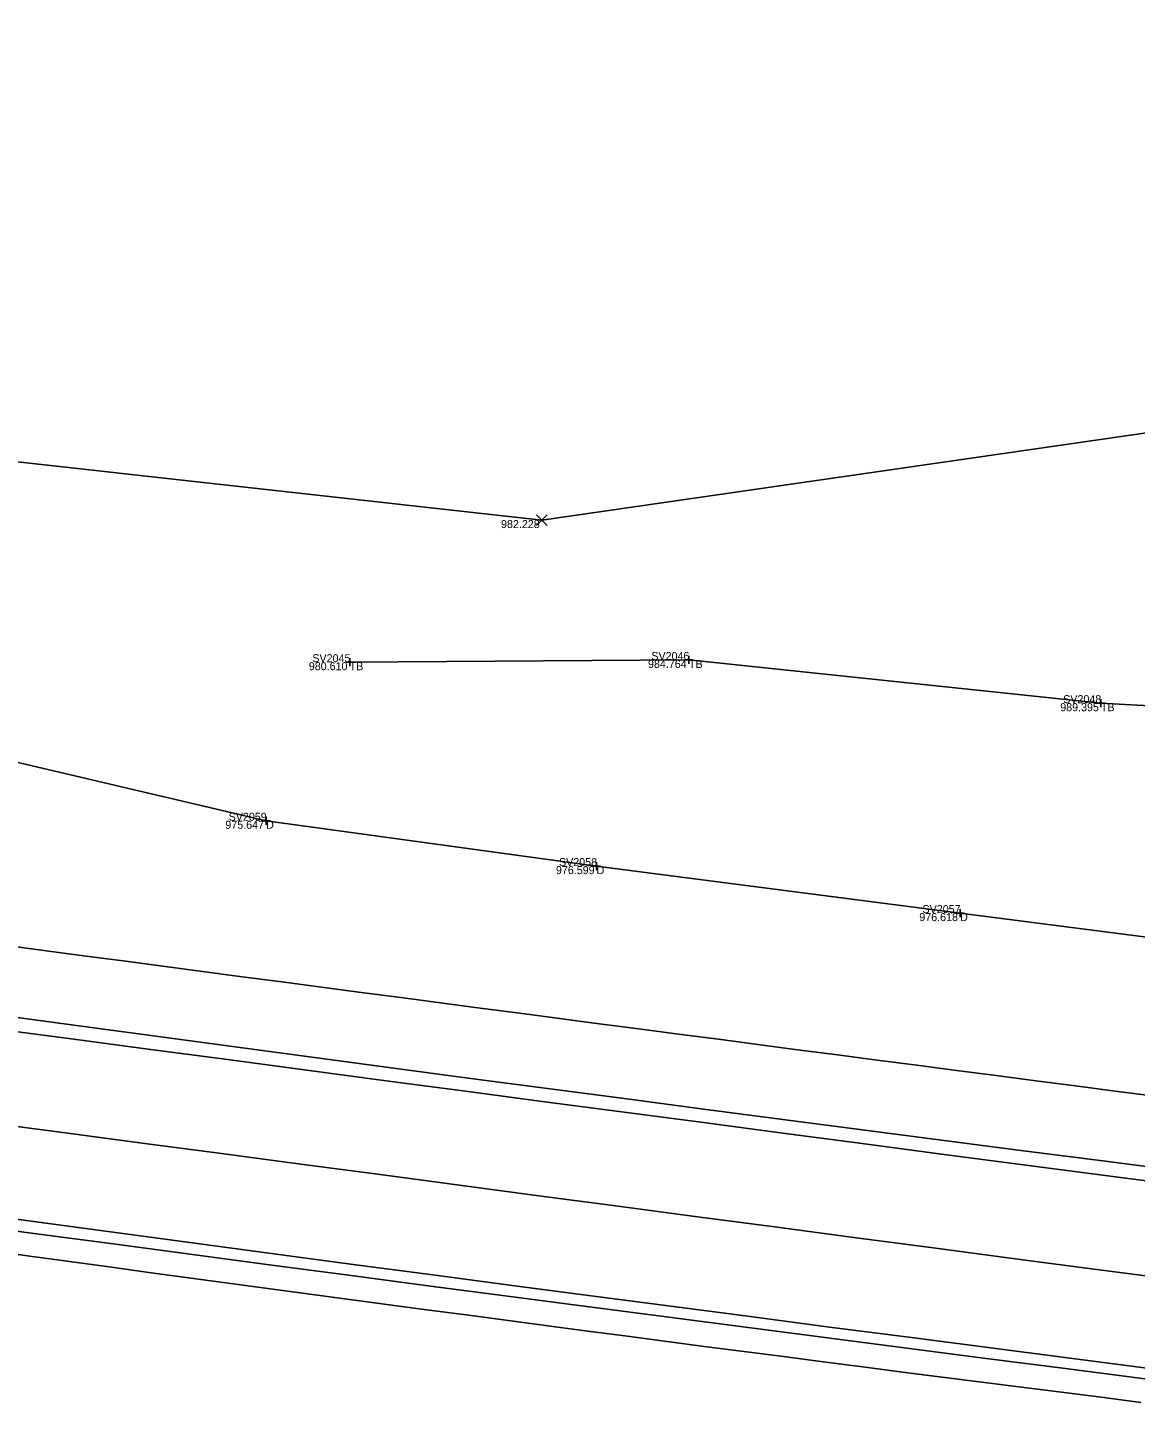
# Model space of a CAD drawing. Extents: x 2065431 to 2068157, y 709104 to 709719.
# Drawn here: x 2066585.2 to 2066723.6, y 709474.3 to 709646.1 of the extents above; entities that cross this region are included whole.
import ezdxf

# ---------------------------------------------------------------- set-up
doc = ezdxf.new("R2010")
doc.units = 0
for name, color, linetype in [('DT_X_Terrain_Boundary', 7, 'Continuous'), ('PM_X_Edge_Line', 7, 'Continuous'), ('PM_X_Lane_Line', 7, 'Continuous'), ('PV_X_EOP', 7, 'Continuous'), ('PV_X_Shoulder_Rumble_Strip', 7, 'Continuous'), ('RS_Raster1', 7, 'Continuous'), ('RW_X_CL_100_Bearings', 7, 'Continuous'), ('RW_X_Fee_WL', 7, 'Continuous'), ('SV_X_Mon_Cells_Found', 7, 'Continuous'), ('SV_X_Text_Elevation', 7, 'Continuous'), ('SV_X_Text_Name', 7, 'Continuous'), ('SV_X_Top_of_Bank', 7, 'Continuous')]:
    doc.layers.add(name, color=color, linetype=linetype)

msp = doc.modelspace()

# ---------------------------------------------------------------- linework, layer by layer
at = {"layer": 'DT_X_Terrain_Boundary'}
msp.add_lwpolyline([(2066859.95, 709495.56), (2066834.34, 709517.99), (2066832.56, 709534.67), (2066834.65, 709554.72), (2066795.22, 709561.14), (2066752.69, 709599.48), (2066649.44, 709584.58), (2066543.44, 709596.37)], dxfattribs=at)
at = {"layer": 'PM_X_Edge_Line'}
for points in [[(2066580.41, 709521.11), (2066590.32, 709519.79), (2066600.23, 709518.47), (2066610.15, 709517.16), (2066620.06, 709515.84), (2066629.97, 709514.53), (2066639.89, 709513.22), (2066649.8, 709511.91), (2066659.71, 709510.6), (2066669.63, 709509.29), (2066679.54, 709507.98), (2066689.46, 709506.67), (2066699.37, 709505.36), (2066709.29, 709504.06), (2066719.2, 709502.76), (2066729.12, 709501.47)], [(2066576.33, 709498.23), (2066586.24, 709496.89), (2066596.15, 709495.55), (2066606.06, 709494.22), (2066615.97, 709492.9), (2066625.88, 709491.58), (2066635.8, 709490.26), (2066645.71, 709488.95), (2066655.62, 709487.65), (2066665.54, 709486.34), (2066675.45, 709485.05), (2066685.37, 709483.75), (2066695.29, 709482.47), (2066705.2, 709481.18), (2066715.12, 709479.91), (2066725.04, 709478.63)]]:
    msp.add_lwpolyline(points, dxfattribs=at)
at = {"layer": 'PM_X_Lane_Line'}
msp.add_lwpolyline([(2066579.69, 709509.37), (2066589.6, 709508.05), (2066599.51, 709506.74), (2066609.42, 709505.42), (2066619.34, 709504.1), (2066629.25, 709502.79), (2066639.16, 709501.47), (2066649.08, 709500.16), (2066658.99, 709498.85), (2066668.9, 709497.53), (2066678.82, 709496.22), (2066688.73, 709494.91), (2066698.65, 709493.6), (2066708.56, 709492.29), (2066718.47, 709490.98), (2066728.39, 709489.68)], dxfattribs=at)
at = {"layer": 'PV_X_EOP'}
for points in [[(2066582.26, 709531.46), (2066587.21, 709530.8), (2066592.17, 709530.15), (2066597.13, 709529.49), (2066602.08, 709528.83), (2066607.04, 709528.18), (2066612, 709527.52), (2066616.96, 709526.87), (2066621.91, 709526.21), (2066626.87, 709525.56), (2066631.83, 709524.91), (2066636.78, 709524.25), (2066641.74, 709523.6), (2066646.7, 709522.95), (2066651.66, 709522.3), (2066656.61, 709521.65), (2066661.57, 709521), (2066666.53, 709520.35), (2066671.49, 709519.7), (2066676.44, 709519.05), (2066681.4, 709518.4), (2066686.36, 709517.76), (2066691.32, 709517.11), (2066696.28, 709516.46), (2066701.23, 709515.82), (2066706.19, 709515.17), (2066711.15, 709514.53), (2066716.11, 709513.89), (2066721.07, 709513.24), (2066726.03, 709512.6)], [(2066580.52, 709493.3), (2066585.47, 709492.62), (2066590.43, 709491.94), (2066595.38, 709491.26), (2066600.33, 709490.58), (2066605.29, 709489.91), (2066610.24, 709489.24), (2066615.2, 709488.57), (2066620.15, 709487.9), (2066625.11, 709487.24), (2066630.06, 709486.58), (2066635.02, 709485.91), (2066639.98, 709485.26), (2066644.93, 709484.6), (2066649.89, 709483.94), (2066654.85, 709483.29), (2066659.81, 709482.64), (2066664.76, 709481.99), (2066669.72, 709481.34), (2066674.68, 709480.7), (2066679.64, 709480.05), (2066684.6, 709479.41), (2066689.55, 709478.77), (2066694.51, 709478.13), (2066699.47, 709477.5), (2066704.43, 709476.87), (2066709.39, 709476.23), (2066714.35, 709475.6), (2066719.31, 709474.97), (2066724.27, 709474.32)]]:
    msp.add_lwpolyline(points, dxfattribs=at)
at = {"layer": 'PV_X_Shoulder_Rumble_Strip'}
for points in [[(2066580.75, 709522.83), (2066590.66, 709521.49), (2066600.57, 709520.16), (2066610.48, 709518.83), (2066620.39, 709517.5), (2066630.31, 709516.18), (2066640.22, 709514.86), (2066650.13, 709513.55), (2066660.05, 709512.25), (2066669.96, 709510.94), (2066679.88, 709509.64), (2066689.79, 709508.35), (2066699.71, 709507.06), (2066709.63, 709505.78), (2066719.54, 709504.5), (2066729.46, 709503.21)], [(2066576.07, 709496.78), (2066585.98, 709495.45), (2066595.89, 709494.13), (2066605.8, 709492.81), (2066615.72, 709491.49), (2066625.63, 709490.18), (2066635.54, 709488.87), (2066645.46, 709487.57), (2066655.37, 709486.27), (2066665.29, 709484.98), (2066675.21, 709483.69), (2066685.12, 709482.4), (2066695.04, 709481.12), (2066704.96, 709479.84), (2066714.88, 709478.57), (2066724.8, 709477.29)]]:
    msp.add_lwpolyline(points, dxfattribs=at)
at = {"layer": 'RS_Raster1'}
for p, q in [((2066625.43, 709567.32), (2066625.43, 709566.32)), ((2066667.32, 709567.1), (2066668.32, 709567.1)), ((2066667.82, 709567.6), (2066667.82, 709566.6)), ((2066667.82, 709567.1), (2066667.82, 709567.1)), ((2066624.93, 709566.82), (2066625.93, 709566.82)), ((2066625.43, 709566.82), (2066625.43, 709566.82)), ((2066719.28, 709562.2), (2066719.28, 709561.2)), ((2066718.78, 709561.7), (2066719.78, 709561.7)), ((2066719.28, 709561.7), (2066719.28, 709561.7)), ((2066614.48, 709547.01), (2066615.48, 709547.01)), ((2066614.98, 709547.51), (2066614.98, 709546.51)), ((2066614.98, 709547.01), (2066614.98, 709547.01)), ((2066655.78, 709541.34), (2066656.78, 709541.34)), ((2066656.28, 709541.84), (2066656.28, 709540.84)), ((2066656.28, 709541.34), (2066656.28, 709541.34)), ((2066701.2, 709535.47), (2066702.2, 709535.47)), ((2066701.7, 709535.97), (2066701.7, 709534.97)), ((2066701.7, 709535.47), (2066701.7, 709535.47))]:
    msp.add_line(p, q, dxfattribs=at)
at = {"layer": 'RW_X_CL_100_Bearings'}
for p, q in [((2066648.78, 709583.91), (2066650.11, 709585.25)), ((2066648.78, 709585.25), (2066650.11, 709583.91))]:
    msp.add_line(p, q, dxfattribs=at)
at = {"layer": 'RW_X_Fee_WL'}
msp.add_lwpolyline([(2066834.34, 709517.99), (2066792.15, 709523.14), (2066747.37, 709529.6), (2066701.7, 709535.47), (2066656.28, 709541.34), (2066614.98, 709547.01), (2066577.22, 709555.89), (2066538.15, 709580.88), (2066497.57, 709596.35), (2066445.11, 709628.08), (2066445.1, 709628.08), (2066425.53, 709638.57), (2066410.9, 709640.69), (2066399.97, 709646.12), (2066394.4, 709644.52), (2066392.47, 709644.49), (2066393.15, 709634.42)], dxfattribs=at)
at = {"layer": 'SV_X_Top_of_Bank'}
msp.add_lwpolyline([(2066625.43, 709566.82), (2066667.82, 709567.1), (2066719.28, 709561.7), (2066756.55, 709559.68), (2066795.22, 709561.14), (2066834.65, 709554.72)], dxfattribs=at)

# ---------------------------------------------------------------- texts
at = {"layer": 'SV_X_Mon_Cells_Found'}
for s, p in [('SV2045', (2066620.76, 709566.82)), ('SV2046', (2066663.12, 709567.1)), ('SV2048', (2066714.58, 709561.7)), ('SV2059', (2066610.3, 709547.01)), ('SV2058', (2066651.58, 709541.34)), ('SV2057', (2066697, 709535.47))]:
    msp.add_text(s, height=1, dxfattribs=at).set_placement(p)
at = {"layer": 'SV_X_Text_Elevation'}
for s, p in [('TB', (2066667.82, 709566.1)), ('TB', (2066625.43, 709565.82)), ('TB', (2066719.28, 709560.7)), ('D', (2066614.98, 709546.01)), ('D', (2066656.28, 709540.34)), ('D', (2066701.7, 709534.47))]:
    msp.add_text(s, height=1, dxfattribs=at).set_placement(p)
at = {"layer": 'SV_X_Text_Name'}
for s, p in [('982.228', (2066644.34, 709583.58)), ('984.764', (2066662.7, 709566.1)), ('980.610', (2066620.32, 709565.82)), ('989.395', (2066714.21, 709560.7)), ('975.647', (2066609.89, 709546.01)), ('976.599', (2066651.2, 709540.34)), ('976.618', (2066696.6, 709534.47))]:
    msp.add_text(s, height=1, dxfattribs=at).set_placement(p)

doc.saveas('drawing.dxf')
